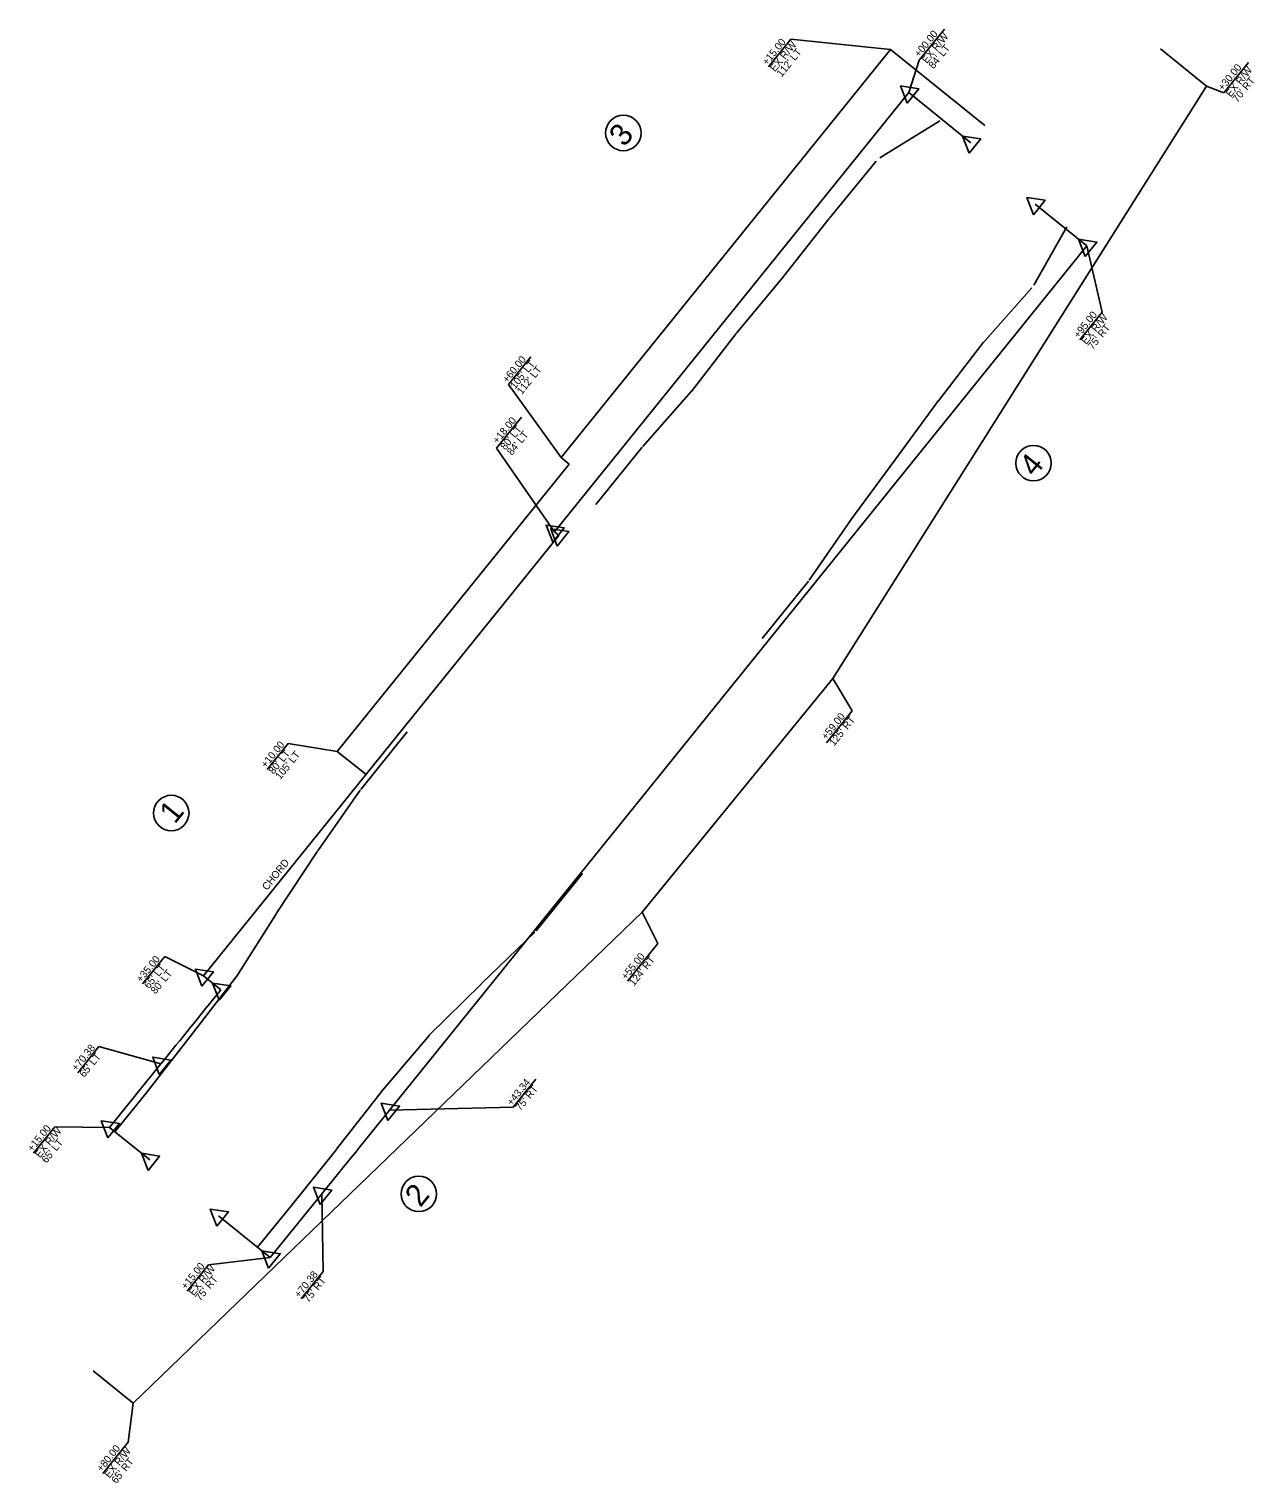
# Model space of a CAD drawing. Extents: x 2293501 to 2295123, y 893006 to 896230.
# Drawn here: x 2293501 to 2294330, y 893006 to 893990 of the extents above; entities that cross this region are included whole.
import ezdxf

# ---------------------------------------------------------------- set-up
doc = ezdxf.new("R2010")
doc.units = 0
for name, color, linetype in [('Prop Easement Construction', 7, 'Continuous'), ('Prop Easement Construction Station Offsets', 7, 'Continuous'), ('Prop Easement Permanent Drainage', 7, 'Continuous'), ('Prop Parcel Number CELL', 7, 'Continuous'), ('Prop ROW Marker CELL', 7, 'Continuous'), ('Prop ROW RW Lines', 7, 'Continuous'), ('Prop ROW Station Offsets', 7, 'Continuous'), ('Scratch_Level_0', 7, 'Continuous')]:
    doc.layers.add(name, color=color, linetype=linetype)

msp = doc.modelspace()

# ---------------------------------------------------------------- linework, layer by layer
at = {"layer": 'Prop Easement Construction'}
for p, q in [((2293861.29, 893699.86), (2294084.23, 893976.12)), ((2294148.04, 893924.63), (2294084.23, 893976.12)), ((2294298.09, 893951.32), (2294266.96, 893976.44)), ((2294045.09, 893550.24), (2294298.09, 893951.32)), ((2293709.73, 893500.92), (2293866.73, 893695.47)), ((2293866.73, 893695.47), (2293861.29, 893699.86)), ((2293916.2, 893392.12), (2294045.09, 893550.24)), ((2293729.18, 893485.22), (2293709.73, 893500.92)), ((2293571.66, 893059.66), (2293916.2, 893392.12)), ((2293571.66, 893059.66), (2293544.45, 893081.68))]:
    msp.add_line(p, q, dxfattribs=at)
at = {"layer": 'Prop Easement Construction Station Offsets'}
for p, q in [((2294016.67, 893982.99), (2294001.56, 893964.28)), ((2294326.47, 893967.34), (2294309.76, 893946.65)), ((2294298.09, 893951.32), (2294309.76, 893946.65)), ((2293840.78, 893768.1), (2293825.67, 893749.39)), ((2294045.09, 893550.24), (2294058.23, 893528.31)), ((2294058.23, 893528.31), (2294040.88, 893506.82)), ((2293676.43, 893506.36), (2293662.17, 893488.7)), ((2293916.2, 893392.12), (2293926.79, 893370.92)), ((2293926.79, 893370.92), (2293906.11, 893345.31)), ((2293571.66, 893059.66), (2293568.13, 893033.3)), ((2293568.13, 893033.3), (2293551.08, 893012.19))]:
    msp.add_line(p, q, dxfattribs=at)
for points in [[(2294016.67, 893982.99), (2294084.23, 893976.12)], [(2293825.67, 893749.39), (2293861.29, 893699.86)], [(2293676.43, 893506.36), (2293709.73, 893500.92)]]:
    msp.add_lwpolyline(points, dxfattribs=at)
at = {"layer": 'Prop Easement Permanent Drainage'}
for p, q in [((2294096.6, 893946.87), (2294096.6, 893946.87)), ((2293859.81, 893647.08), (2293856.7, 893649.59))]:
    msp.add_line(p, q, dxfattribs=at)
at = {"layer": 'Prop Parcel Number CELL'}
for p, q in [((2293903.39, 893919.56), (2293903.39, 893919.56)), ((2294181.05, 893696.09), (2294181.05, 893696.09)), ((2293597.38, 893459.22), (2293597.38, 893459.22)), ((2293764.94, 893201.37), (2293764.94, 893201.37))]:
    msp.add_line(p, q, dxfattribs=at)
for centre in [(2293903.39, 893919.56), (2294181.05, 893696.09), (2293597.38, 893459.22), (2293764.94, 893201.37)]:
    msp.add_circle(centre, 12, dxfattribs=at)
at = {"layer": 'Prop ROW Marker CELL'}
for p, q in [((2294096.6, 893946.87), (2294096.6, 893946.87)), ((2294138.62, 893912.95), (2294138.62, 893912.95)), ((2294182.18, 893871.38), (2294182.18, 893871.38)), ((2294217.19, 893843.12), (2294217.19, 893843.12)), ((2293856.7, 893649.59), (2293856.7, 893649.59)), ((2293859.81, 893647.08), (2293859.81, 893647.08)), ((2293619.29, 893349.04), (2293619.29, 893349.04)), ((2293630.96, 893339.62), (2293630.96, 893339.62)), ((2293590.39, 893289.43), (2293590.39, 893289.43)), ((2293745.14, 893258.18), (2293745.14, 893258.18)), ((2293555.55, 893246.38), (2293555.55, 893246.38)), ((2293582.75, 893224.36), (2293582.75, 893224.36)), ((2293699.21, 893201.35), (2293699.21, 893201.35)), ((2293629.39, 893186.61), (2293629.39, 893186.61)), ((2293664.37, 893158.3), (2293664.37, 893158.3))]:
    msp.add_line(p, q, dxfattribs=at)
for points in [[(2294095.47, 893939.74), (2294091, 893951.39), (2294103.33, 893949.47)], [(2294137.5, 893905.83), (2294133.02, 893917.48), (2294145.35, 893915.55)], [(2294181.05, 893864.26), (2294176.57, 893875.9), (2294188.9, 893873.98)], [(2294216.07, 893836), (2294211.59, 893847.64), (2294223.92, 893845.72)], [(2293855.57, 893642.47), (2293851.1, 893654.12), (2293863.43, 893652.19)], [(2293858.69, 893639.96), (2293854.21, 893651.6), (2293866.54, 893649.68)], [(2293618.16, 893341.92), (2293613.69, 893353.56), (2293626.02, 893351.64)], [(2293629.83, 893332.49), (2293625.36, 893344.14), (2293637.69, 893342.22)], [(2293589.26, 893282.3), (2293584.79, 893293.95), (2293597.12, 893292.03)], [(2293744.02, 893251.06), (2293739.54, 893262.7), (2293751.87, 893260.78)], [(2293554.42, 893239.26), (2293549.95, 893250.91), (2293562.28, 893248.98)], [(2293581.63, 893217.24), (2293577.15, 893228.89), (2293589.48, 893226.96)], [(2293698.08, 893194.22), (2293693.61, 893205.87), (2293705.94, 893203.95)], [(2293628.26, 893179.49), (2293623.79, 893191.14), (2293636.12, 893189.22)], [(2293663.24, 893151.18), (2293658.77, 893162.83), (2293671.09, 893160.9)]]:
    msp.add_lwpolyline(points, close=True, dxfattribs=at)
at = {"layer": 'Prop ROW RW Lines'}
for p, q in [((2293856.7, 893649.59), (2294096.6, 893946.87)), ((2294138.62, 893912.95), (2294096.6, 893946.87)), ((2294217.19, 893843.12), (2294182.18, 893871.38)), ((2293745.14, 893258.18), (2294217.19, 893843.12)), ((2293619.29, 893349.04), (2293859.81, 893647.08)), ((2293859.81, 893647.08), (2293856.7, 893649.59)), ((2293630.96, 893339.62), (2293619.29, 893349.04)), ((2293555.55, 893246.38), (2293590.39, 893289.43)), ((2293582.75, 893224.36), (2293555.55, 893246.38)), ((2293664.37, 893158.3), (2293699.21, 893201.35)), ((2293664.37, 893158.3), (2293629.39, 893186.61))]:
    msp.add_line(p, q, dxfattribs=at)
for radius, end in [(49935, 321.086523), (50075, 321.096083)]:
    msp.add_arc((2254776.77, 924706.09), radius, 321.012472, end, dxfattribs=at)
at = {"layer": 'Prop ROW Station Offsets'}
for p, q in [((2294120.69, 893989.9), (2294103.66, 893968.82)), ((2294103.66, 893968.82), (2294096.6, 893946.87)), ((2294227.41, 893798.35), (2294212.3, 893779.64)), ((2293834.52, 893727.29), (2293817.5, 893706.21)), ((2293856.7, 893649.59), (2293817.5, 893706.21)), ((2293592.97, 893362.2), (2293577.86, 893343.49)), ((2293548.42, 893301.22), (2293534.06, 893283.44)), ((2293548.42, 893301.22), (2293590.39, 893289.43)), ((2293844.15, 893279.16), (2293828.72, 893260.06)), ((2293745.14, 893258.18), (2293828.72, 893260.06)), ((2293518.44, 893246.73), (2293504.09, 893228.95)), ((2293699.21, 893201.35), (2293700.14, 893148.82)), ((2293622.5, 893153.42), (2293608.14, 893135.64)), ((2293700.14, 893148.82), (2293685.27, 893130.41))]:
    msp.add_line(p, q, dxfattribs=at)
for points in [[(2294227.41, 893798.35), (2294217.19, 893843.12)], [(2293592.97, 893362.2), (2293619.29, 893349.04)], [(2293518.44, 893246.73), (2293555.55, 893246.38)], [(2293622.5, 893153.42), (2293664.37, 893158.3)]]:
    msp.add_lwpolyline(points, dxfattribs=at)
at = {"layer": 'Scratch_Level_0'}
for p, q in [((2294117.7, 893927.7), (2294077.06, 893902.67)), ((2294042.88, 893861.82), (2294074.57, 893900.49)), ((2294011.78, 893822.42), (2294042.76, 893861.67)), ((2294203.69, 893856.1), (2294181.17, 893816.44)), ((2293980.06, 893784.07), (2294011.93, 893822.6)), ((2294146.7, 893777.32), (2294179.95, 893814.74)), ((2293949.22, 893744.3), (2293979.86, 893783.82)), ((2294116.69, 893738.21), (2294147.16, 893777.88)), ((2293916.5, 893707.27), (2293949.62, 893744.79)), ((2294087.15, 893698.06), (2294116.82, 893738.37)), ((2293884.81, 893668.03), (2293916.21, 893706.94)), ((2294057.47, 893657.76), (2294087.14, 893698.06)), ((2294029.07, 893616.79), (2294057.64, 893657.99)), ((2293997.24, 893577.3), (2294028.64, 893616.21)), ((2293725.61, 893475.25), (2293757, 893514.16)), ((2293696.56, 893433.53), (2293725.18, 893474.68)), ((2293668.7, 893391.47), (2293696.43, 893433.34)), ((2293844.33, 893379.44), (2293875.73, 893418.35)), ((2293641.66, 893348.77), (2293668.59, 893391.3)), ((2293807.18, 893343.56), (2293843.48, 893378.52)), ((2293611.74, 893309.89), (2293642.18, 893349.52)), ((2293771.49, 893308.29), (2293807.27, 893343.66)), ((2293581.08, 893270.5), (2293611.78, 893309.94)), ((2293739.78, 893270.76), (2293772.09, 893308.94)), ((2293581.2, 893270.65), (2293559.18, 893243.45)), ((2293709.18, 893231.64), (2293740.02, 893271.06)), ((2293677.79, 893192.52), (2293709.1, 893231.55)), ((2293655.75, 893165.28), (2293677.77, 893192.49))]:
    msp.add_line(p, q, dxfattribs=at)

# ---------------------------------------------------------------- texts
at = {"layer": 'Prop Easement Construction Station Offsets'}
for s, p in [('+15.00', (2294000.76, 893964.93)), ('EX R/W', (2294006.04, 893960.66)), ("112' LT", (2294010.54, 893957.02)), ('+30.00', (2294309.29, 893947.72)), ('EX R/W', (2294314.56, 893943.46)), ("70' RT", (2294319.08, 893939.81)), ('+60.00', (2293824.89, 893750.03)), ("105' LT", (2293830.11, 893745.81)), ("112' LT", (2293834.66, 893742.14)), ('+59.00', (2294040.83, 893508.41)), ("125' RT", (2294046.07, 893504.17)), ('+10.00', (2293661.41, 893489.32)), ("80' LT", (2293666.64, 893485.09)), ("105' LT", (2293671.14, 893481.46)), ('+55.00', (2293905.31, 893345.96)), ("124' RT", (2293910.56, 893341.72)), ('+80.00', (2293550.19, 893012.91)), ('EX R/W', (2293555.52, 893008.61)), ("65' RT", (2293560.14, 893004.88))]:
    msp.add_text(s, height=5, rotation=51.07477, dxfattribs=at).set_placement(p)
at = {"layer": 'Prop Parcel Number CELL'}
for s, p in [('3', (2293904.12, 893909.53)), ('4', (2294181.83, 893686.13)), ('1', (2293599.76, 893451.25)), ('2', (2293765.97, 893191.72))]:
    msp.add_text(s, height=15, rotation=51.07477, dxfattribs=at).set_placement(p)
at = {"layer": 'Prop ROW Station Offsets'}
for s, p in [('+00.00', (2294103.66, 893970.44)), ('EX R/W', (2294108.89, 893966.22)), ("84' LT", (2294113.32, 893962.64)), ('+95.00', (2294211.48, 893780.3)), ('EX R/W', (2294216.73, 893776.06)), ("75' RT", (2294221.17, 893772.48)), ('+18.00', (2293818.28, 893708.76)), ("80' LT", (2293823.48, 893704.57)), ("84' LT", (2293827.97, 893700.94)), ('CHORD', (2293662.21, 893406.48)), ('+35.00', (2293577.08, 893344.12)), ("65' LT", (2293582.27, 893339.93)), ("80' LT", (2293586.78, 893336.29)), ('+70.38', (2293533.28, 893284.08)), ("65' LT", (2293538.49, 893279.87)), ('+43.34', (2293827.85, 893260.76)), ("75' RT", (2293833.7, 893257.18)), ('+15.00', (2293503.3, 893229.59)), ('EX R/W', (2293508.51, 893225.38)), ("65' LT", (2293512.93, 893221.81)), ('+15.00', (2293607.37, 893136.27)), ('EX R/W', (2293612.58, 893132.07)), ("75' RT", (2293617, 893128.49)), ('+70.38', (2293684.03, 893130.66)), ("75' RT", (2293690.2, 893127.48))]:
    msp.add_text(s, height=5, rotation=51.07477, dxfattribs=at).set_placement(p)

doc.saveas('drawing.dxf')
